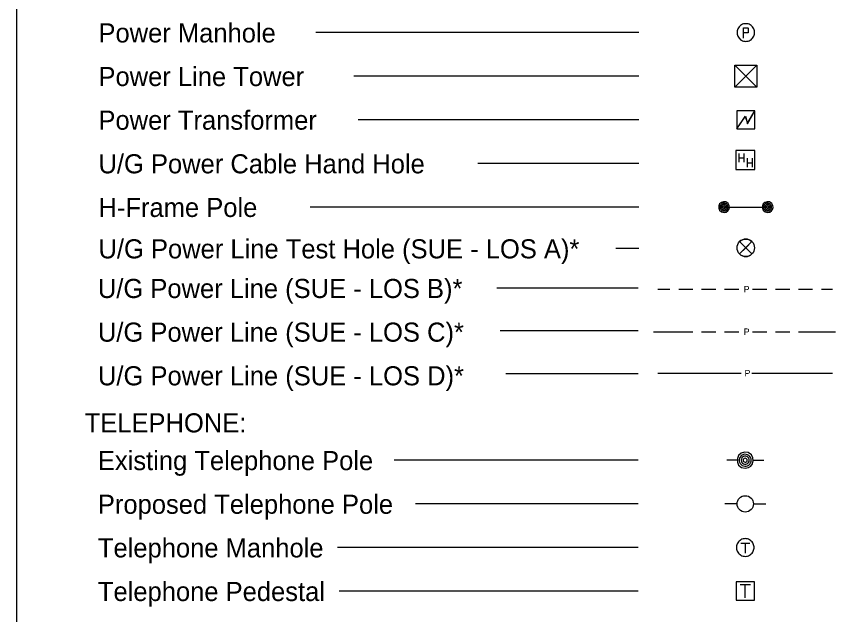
# Model space of a CAD drawing. Extents: x 754056.72 to 754059.56, y 596603.78 to 596605.61.
# Drawn here: x 754058.141 to 754058.773, y 596604.239 to 596604.7 of the extents above; entities that cross this region are included whole.
import ezdxf

# ---------------------------------------------------------------- set-up
doc = ezdxf.new("R2010")
doc.units = 0
for name, color, linetype in [('Exist Utilities Power Test Hole SUE LOS A CELL', 7, 'Continuous'), ('Sheet_Symbology', 7, 'Continuous'), ('z - Construction', 7, 'Continuous')]:
    doc.layers.add(name, color=color, linetype=linetype)

msp = doc.modelspace()

# ---------------------------------------------------------------- linework, layer by layer
at = {"layer": 'Exist Utilities Power Test Hole SUE LOS A CELL'}
for points in [[(754058.7084, 596604.52637), (754058.6989, 596604.51687), (754058.70365, 596604.52162), (754058.6989, 596604.52637), (754058.7084, 596604.51687)], [(754058.6989, 596604.52637), (754058.70365, 596604.52162), (754058.7084, 596604.52637)], [(754058.7084, 596604.51687), (754058.70365, 596604.52162), (754058.6989, 596604.51687)]]:
    msp.add_lwpolyline(points, dxfattribs=at)
msp.add_circle((754058.70365, 596604.52162), 0.00672, dxfattribs=at)
for start, end in [(45, 135), (225, 315)]:
    msp.add_arc((754058.70365, 596604.52162), 0.00672, start, end, dxfattribs=at)
at = {"layer": 'Sheet_Symbology'}
for p, q in [((754058.62127, 596604.68753), (754058.37214, 596604.68753)), ((754058.70505, 596604.68721), (754058.702, 596604.68721)), ((754058.7056, 596604.69064), (754058.7056, 596604.68775)), ((754058.71213, 596604.66234), (754058.69533, 596604.64554)), ((754058.71213, 596604.64554), (754058.69533, 596604.66234)), ((754058.62127, 596604.6539), (754058.40155, 596604.6539)), ((754058.62127, 596604.62027), (754058.40496, 596604.62027)), ((754058.69819, 596604.59436), (754058.69819, 596604.58758)), ((754058.69819, 596604.59091), (754058.70206, 596604.59091)), ((754058.70206, 596604.59436), (754058.70206, 596604.58758)), ((754058.70465, 596604.59067), (754058.70465, 596604.58389)), ((754058.70853, 596604.59067), (754058.70853, 596604.58389)), ((754058.62127, 596604.58664), (754058.49702, 596604.58664)), ((754058.70465, 596604.58722), (754058.70853, 596604.58722)), ((754058.62127, 596604.55301), (754058.36788, 596604.55301)), ((754058.68687, 596604.55301), (754058.72051, 596604.55301)), ((754058.62127, 596604.5211), (754058.60339, 596604.5211)), ((754058.62081, 596604.49055), (754058.51165, 596604.49055)), ((754058.63597, 596604.48972), (754058.64522, 596604.48972)), ((754058.65194, 596604.48972), (754058.66287, 596604.48972)), ((754058.6696, 596604.48972), (754058.68053, 596604.48972)), ((754058.68726, 596604.48972), (754058.69819, 596604.48972)), ((754058.70895, 596604.48972), (754058.71988, 596604.48972)), ((754058.7266, 596604.48972), (754058.73753, 596604.48972)), ((754058.74426, 596604.48972), (754058.75519, 596604.48972)), ((754058.76192, 596604.48972), (754058.77049, 596604.48972)), ((754058.62081, 596604.45756), (754058.51423, 596604.45756)), ((754058.63257, 596604.45692), (754058.66287, 596604.45692)), ((754058.6696, 596604.45692), (754058.68053, 596604.45692)), ((754058.68726, 596604.45692), (754058.69819, 596604.45692)), ((754058.70895, 596604.45692), (754058.71988, 596604.45692)), ((754058.7266, 596604.45692), (754058.73753, 596604.45692)), ((754058.74426, 596604.45692), (754058.77289, 596604.45692)), ((754058.62081, 596604.42457), (754058.51876, 596604.42457)), ((754058.63597, 596604.42504), (754058.70001, 596604.42504)), ((754058.70842, 596604.42504), (754058.77049, 596604.42504)), ((754058.62081, 596604.3579), (754058.43267, 596604.3579)), ((754058.69702, 596604.3579), (754058.68896, 596604.3579)), ((754058.70944, 596604.3579), (754058.71751, 596604.3579)), ((754058.62081, 596604.32426), (754058.44919, 596604.32426)), ((754058.69699, 596604.32424), (754058.68753, 596604.32424)), ((754058.7096, 596604.32424), (754058.71906, 596604.32424)), ((754058.70673, 596604.2938), (754058.69979, 596604.2938)), ((754058.70323, 596604.2938), (754058.70323, 596604.28616)), ((754058.62081, 596604.29063), (754058.38899, 596604.29063)), ((754058.6993, 596604.26207), (754058.70717, 596604.26207)), ((754058.70323, 596604.25194), (754058.70323, 596604.26207)), ((754058.62081, 596604.257), (754058.39017, 596604.257))]:
    msp.add_line(p, q, dxfattribs=at)
for points in [[(754058.70369, 596604.69436), (754058.70282, 596604.6943), (754058.702, 596604.69414), (754058.70118, 596604.69387), (754058.70041, 596604.69348), (754058.6997, 596604.69305), (754058.69905, 596604.6925), (754058.69845, 596604.69185), (754058.69795, 596604.69119), (754058.69752, 596604.69043), (754058.69724, 596604.68961), (754058.69703, 596604.68879), (754058.69692, 596604.68797), (754058.69692, 596604.6871), (754058.69703, 596604.68628), (754058.69724, 596604.6854), (754058.69752, 596604.68464), (754058.69795, 596604.68387), (754058.69845, 596604.68322), (754058.69905, 596604.68256), (754058.6997, 596604.68202), (754058.70041, 596604.68158), (754058.70118, 596604.6812), (754058.702, 596604.68092), (754058.70287, 596604.68076), (754058.70369, 596604.68071), (754058.70456, 596604.68076), (754058.70538, 596604.68092), (754058.7062, 596604.6812), (754058.70697, 596604.68158), (754058.70768, 596604.68202), (754058.70833, 596604.68256), (754058.70893, 596604.68322), (754058.70943, 596604.68387), (754058.70986, 596604.68464), (754058.71014, 596604.68546), (754058.71035, 596604.68628), (754058.71046, 596604.6871), (754058.71046, 596604.68797), (754058.71035, 596604.68879), (754058.71014, 596604.68966), (754058.70986, 596604.69043), (754058.70943, 596604.69119), (754058.70893, 596604.69185), (754058.70833, 596604.6925), (754058.70768, 596604.69305), (754058.70697, 596604.69348), (754058.7062, 596604.69387), (754058.70538, 596604.69414), (754058.70451, 596604.6943), (754058.70369, 596604.69436)], [(754058.702, 596604.68316), (754058.702, 596604.68721), (754058.702, 596604.69119), (754058.70505, 596604.69119)], [(754058.70505, 596604.69119), (754058.70528, 596604.69114), (754058.70544, 596604.69103), (754058.70555, 596604.69087), (754058.7056, 596604.69064)], [(754058.7056, 596604.68775), (754058.70555, 596604.68753), (754058.70544, 596604.68737), (754058.70528, 596604.68726), (754058.70505, 596604.68721)], [(754058.71213, 596604.64554), (754058.69533, 596604.64554), (754058.69533, 596604.66234), (754058.71213, 596604.66234), (754058.71213, 596604.64554), (754058.69533, 596604.64554), (754058.69533, 596604.66234), (754058.71213, 596604.66234), (754058.71213, 596604.64554)], [(754058.69668, 596604.61326), (754058.7033, 596604.62277), (754058.70491, 596604.6176), (754058.7107, 596604.62728)], [(754058.69668, 596604.61326), (754058.70336, 596604.62316), (754058.70486, 596604.61721), (754058.7107, 596604.62728)], [(754058.69668, 596604.61326), (754058.7107, 596604.61326), (754058.7107, 596604.62728), (754058.69668, 596604.62728), (754058.69668, 596604.61326)], [(754058.6961, 596604.58203), (754058.71058, 596604.58203), (754058.71058, 596604.59651), (754058.6961, 596604.59651), (754058.6961, 596604.58203)], [(754058.68994, 596604.55301), (754058.68985, 596604.55375), (754058.6896, 596604.55441), (754058.68919, 596604.55499), (754058.68869, 596604.55549), (754058.68812, 596604.55582), (754058.68737, 596604.55599), (754058.68671, 596604.55607), (754058.68596, 596604.5559), (754058.6853, 596604.55566), (754058.68481, 596604.55524), (754058.68431, 596604.55466), (754058.68398, 596604.55408), (754058.68381, 596604.55334), (754058.68381, 596604.55268), (754058.68398, 596604.55193), (754058.68431, 596604.55135), (754058.68481, 596604.55077), (754058.6853, 596604.55036), (754058.68596, 596604.55011), (754058.68671, 596604.54994), (754058.68737, 596604.55003), (754058.68812, 596604.55019), (754058.68869, 596604.55053), (754058.68919, 596604.55102), (754058.6896, 596604.5516), (754058.68985, 596604.55226), (754058.68994, 596604.55301)], [(754058.68894, 596604.55301), (754058.68886, 596604.55359), (754058.68861, 596604.55416), (754058.6882, 596604.55458), (754058.6877, 596604.55491), (754058.68721, 596604.55508), (754058.68654, 596604.55508), (754058.68605, 596604.55491), (754058.68555, 596604.55458), (754058.68514, 596604.55416), (754058.68489, 596604.55359), (754058.68481, 596604.55301), (754058.68489, 596604.55243), (754058.68514, 596604.55185), (754058.68555, 596604.55143), (754058.68605, 596604.5511), (754058.68654, 596604.55094), (754058.68721, 596604.55094), (754058.6877, 596604.5511), (754058.6882, 596604.55143), (754058.68861, 596604.55185), (754058.68886, 596604.55243), (754058.68894, 596604.55301)], [(754058.68787, 596604.55301), (754058.68779, 596604.55342), (754058.68754, 596604.55375), (754058.68721, 596604.55392), (754058.68679, 596604.554), (754058.68638, 596604.55384), (754058.68605, 596604.55359), (754058.68588, 596604.55317), (754058.68588, 596604.55284), (754058.68605, 596604.55243), (754058.68638, 596604.55218), (754058.68679, 596604.55201), (754058.68721, 596604.5521), (754058.68754, 596604.55226), (754058.68779, 596604.55259), (754058.68787, 596604.55301)], [(754058.72357, 596604.55301), (754058.72348, 596604.55375), (754058.72324, 596604.55441), (754058.72282, 596604.55499), (754058.72232, 596604.55549), (754058.72175, 596604.55582), (754058.721, 596604.55599), (754058.72034, 596604.55607), (754058.71959, 596604.5559), (754058.71893, 596604.55566), (754058.71844, 596604.55524), (754058.71794, 596604.55466), (754058.71761, 596604.55408), (754058.71744, 596604.55334), (754058.71744, 596604.55268), (754058.71761, 596604.55193), (754058.71794, 596604.55135), (754058.71844, 596604.55077), (754058.71893, 596604.55036), (754058.71959, 596604.55011), (754058.72034, 596604.54994), (754058.721, 596604.55003), (754058.72175, 596604.55019), (754058.72232, 596604.55053), (754058.72282, 596604.55102), (754058.72324, 596604.5516), (754058.72348, 596604.55226), (754058.72357, 596604.55301)], [(754058.72257, 596604.55301), (754058.72249, 596604.55359), (754058.72224, 596604.55416), (754058.72183, 596604.55458), (754058.72133, 596604.55491), (754058.72084, 596604.55508), (754058.72017, 596604.55508), (754058.71968, 596604.55491), (754058.71918, 596604.55458), (754058.71877, 596604.55416), (754058.71852, 596604.55359), (754058.71844, 596604.55301), (754058.71852, 596604.55243), (754058.71877, 596604.55185), (754058.71918, 596604.55143), (754058.71968, 596604.5511), (754058.72017, 596604.55094), (754058.72084, 596604.55094), (754058.72133, 596604.5511), (754058.72183, 596604.55143), (754058.72224, 596604.55185), (754058.72249, 596604.55243), (754058.72257, 596604.55301)], [(754058.7215, 596604.55301), (754058.72142, 596604.55342), (754058.72117, 596604.55375), (754058.72084, 596604.55392), (754058.72042, 596604.554), (754058.72001, 596604.55384), (754058.71968, 596604.55359), (754058.71951, 596604.55317), (754058.71951, 596604.55284), (754058.71968, 596604.55243), (754058.72001, 596604.55218), (754058.72042, 596604.55201), (754058.72084, 596604.5521), (754058.72117, 596604.55226), (754058.72142, 596604.55259), (754058.7215, 596604.55301)], [(754058.70783, 596604.3579), (754058.7077, 596604.35901), (754058.70733, 596604.36001), (754058.70671, 596604.36088), (754058.70596, 596604.36162), (754058.70509, 596604.36212), (754058.70397, 596604.36236), (754058.70298, 596604.36249), (754058.70186, 596604.36224), (754058.70087, 596604.36187), (754058.70013, 596604.36125), (754058.69939, 596604.36038), (754058.69889, 596604.35951), (754058.69864, 596604.35839), (754058.69864, 596604.3574), (754058.69889, 596604.35628), (754058.69939, 596604.35541), (754058.70013, 596604.35454), (754058.70087, 596604.35392), (754058.70186, 596604.35355), (754058.70298, 596604.3533), (754058.70397, 596604.35343), (754058.70509, 596604.35367), (754058.70596, 596604.35417), (754058.70671, 596604.35492), (754058.70733, 596604.35579), (754058.7077, 596604.35678), (754058.70783, 596604.3579)], [(754058.70633, 596604.3579), (754058.70621, 596604.35877), (754058.70584, 596604.35963), (754058.70522, 596604.36026), (754058.70447, 596604.36075), (754058.70373, 596604.361), (754058.70273, 596604.361), (754058.70199, 596604.36075), (754058.70124, 596604.36026), (754058.70063, 596604.35963), (754058.70025, 596604.35877), (754058.70013, 596604.3579), (754058.70025, 596604.35703), (754058.70063, 596604.35616), (754058.70124, 596604.35554), (754058.70199, 596604.35504), (754058.70273, 596604.35479), (754058.70373, 596604.35479), (754058.70447, 596604.35504), (754058.70522, 596604.35554), (754058.70584, 596604.35616), (754058.70621, 596604.35703), (754058.70633, 596604.3579)], [(754058.70472, 596604.3579), (754058.7046, 596604.35852), (754058.70422, 596604.35901), (754058.70373, 596604.35926), (754058.70311, 596604.35939), (754058.70249, 596604.35914), (754058.70199, 596604.35877), (754058.70174, 596604.35815), (754058.70174, 596604.35765), (754058.70199, 596604.35703), (754058.70249, 596604.35665), (754058.70311, 596604.35641), (754058.70373, 596604.35653), (754058.70422, 596604.35678), (754058.7046, 596604.35728), (754058.70472, 596604.3579)], [(754058.70323, 596604.29746), (754058.70236, 596604.29741), (754058.70154, 596604.29724), (754058.70072, 596604.29697), (754058.69995, 596604.29659), (754058.69924, 596604.29615), (754058.69859, 596604.2956), (754058.69799, 596604.29495), (754058.6975, 596604.29429), (754058.69706, 596604.29353), (754058.69679, 596604.29271), (754058.69657, 596604.29189), (754058.69646, 596604.29107), (754058.69646, 596604.2902), (754058.69657, 596604.28938), (754058.69679, 596604.28851), (754058.69706, 596604.28774), (754058.6975, 596604.28697), (754058.69799, 596604.28632), (754058.69859, 596604.28566), (754058.69924, 596604.28512), (754058.69995, 596604.28468), (754058.70072, 596604.2843), (754058.70154, 596604.28402), (754058.70241, 596604.28386), (754058.70323, 596604.28381), (754058.7041, 596604.28386), (754058.70492, 596604.28402), (754058.70574, 596604.2843), (754058.70651, 596604.28468), (754058.70722, 596604.28512), (754058.70787, 596604.28566), (754058.70848, 596604.28632), (754058.70897, 596604.28697), (754058.7094, 596604.28774), (754058.70968, 596604.28856), (754058.70989, 596604.28938), (754058.71, 596604.2902), (754058.71, 596604.29107), (754058.70989, 596604.29189), (754058.70968, 596604.29276), (754058.7094, 596604.29353), (754058.70897, 596604.29429), (754058.70848, 596604.29495), (754058.70787, 596604.2956), (754058.70722, 596604.29615), (754058.70651, 596604.29659), (754058.70574, 596604.29697), (754058.70492, 596604.29724), (754058.70405, 596604.29741), (754058.70323, 596604.29746)], [(754058.69615, 596604.24993), (754058.71031, 596604.24993), (754058.71031, 596604.26408), (754058.69615, 596604.26408), (754058.69615, 596604.24993)]]:
    msp.add_lwpolyline(points, dxfattribs=at)
for points in [[(754058.68687, 596604.54887), (754058.68861, 596604.5492), (754058.68977, 596604.55003), (754058.69068, 596604.55119), (754058.69101, 596604.55276), (754058.69085, 596604.55425), (754058.69002, 596604.55574), (754058.68837, 596604.55698), (754058.68646, 596604.55715), (754058.68481, 596604.55665), (754058.68348, 596604.55549), (754058.68282, 596604.55392), (754058.68282, 596604.5521), (754058.68348, 596604.55053), (754058.68497, 596604.54928)], [(754058.72051, 596604.54887), (754058.72224, 596604.5492), (754058.7234, 596604.55003), (754058.72431, 596604.55119), (754058.72464, 596604.55276), (754058.72448, 596604.55425), (754058.72365, 596604.55574), (754058.722, 596604.55698), (754058.72009, 596604.55715), (754058.71844, 596604.55665), (754058.71711, 596604.55549), (754058.71645, 596604.55392), (754058.71645, 596604.5521), (754058.71711, 596604.55053), (754058.7186, 596604.54928)], [(754058.70323, 596604.35169), (754058.70584, 596604.35218), (754058.70758, 596604.35343), (754058.70894, 596604.35517), (754058.70944, 596604.35752), (754058.70919, 596604.35976), (754058.70795, 596604.36199), (754058.70547, 596604.36385), (754058.70261, 596604.3641), (754058.70013, 596604.36336), (754058.69814, 596604.36162), (754058.69715, 596604.35926), (754058.69715, 596604.35653), (754058.69814, 596604.35417), (754058.70037, 596604.35231)]]:
    msp.add_lwpolyline(points, close=True, dxfattribs=at)
msp.add_circle((754058.70323, 596604.32426), 0.00631, dxfattribs=at)
at = {"layer": 'z - Construction'}
msp.add_line((754058.1415, 596605.54909), (754058.14146, 596603.84076), dxfattribs=at)

# ---------------------------------------------------------------- texts
at = {"layer": 'Sheet_Symbology'}
for s, height, p in [('Power Manhole', 0.0147137, (754058.20471, 596604.6799)), ('Power Line Tower', 0.0147137, (754058.20471, 596604.64629)), ('Power Transformer', 0.0147137, (754058.20469, 596604.61266)), ('U/G Power Cable Hand Hole', 0.0147137, (754058.20473, 596604.57901)), ('H-Frame Pole', 0.0147137, (754058.20473, 596604.54538)), ('U/G Power Line Test Hole (SUE - LOS A)*', 0.0147137, (754058.20473, 596604.51347)), ('U/G Power Line (SUE - LOS B)*', 0.0147137, (754058.20427, 596604.48292)), ('P', 0.00504, (754058.70205, 596604.4872)), ('U/G Power Line (SUE - LOS C)*', 0.0147137, (754058.20431, 596604.44927)), ('P', 0.00504, (754058.70205, 596604.4544)), ('U/G Power Line (SUE - LOS D)*', 0.0147137, (754058.20435, 596604.41562)), ('P', 0.00504, (754058.70271, 596604.42252)), ('TELEPHONE:', 0.014714, (754058.19407, 596604.37934)), ('Existing Telephone Pole', 0.0147137, (754058.20427, 596604.35027)), ('Proposed Telephone Pole', 0.0147137, (754058.20427, 596604.31663)), ('Telephone Manhole', 0.0147137, (754058.20427, 596604.283)), ('Telephone Pedestal', 0.0147137, (754058.20427, 596604.24937))]:
    msp.add_text(s, height=height, dxfattribs=at).set_placement(p)

doc.saveas('drawing.dxf')
